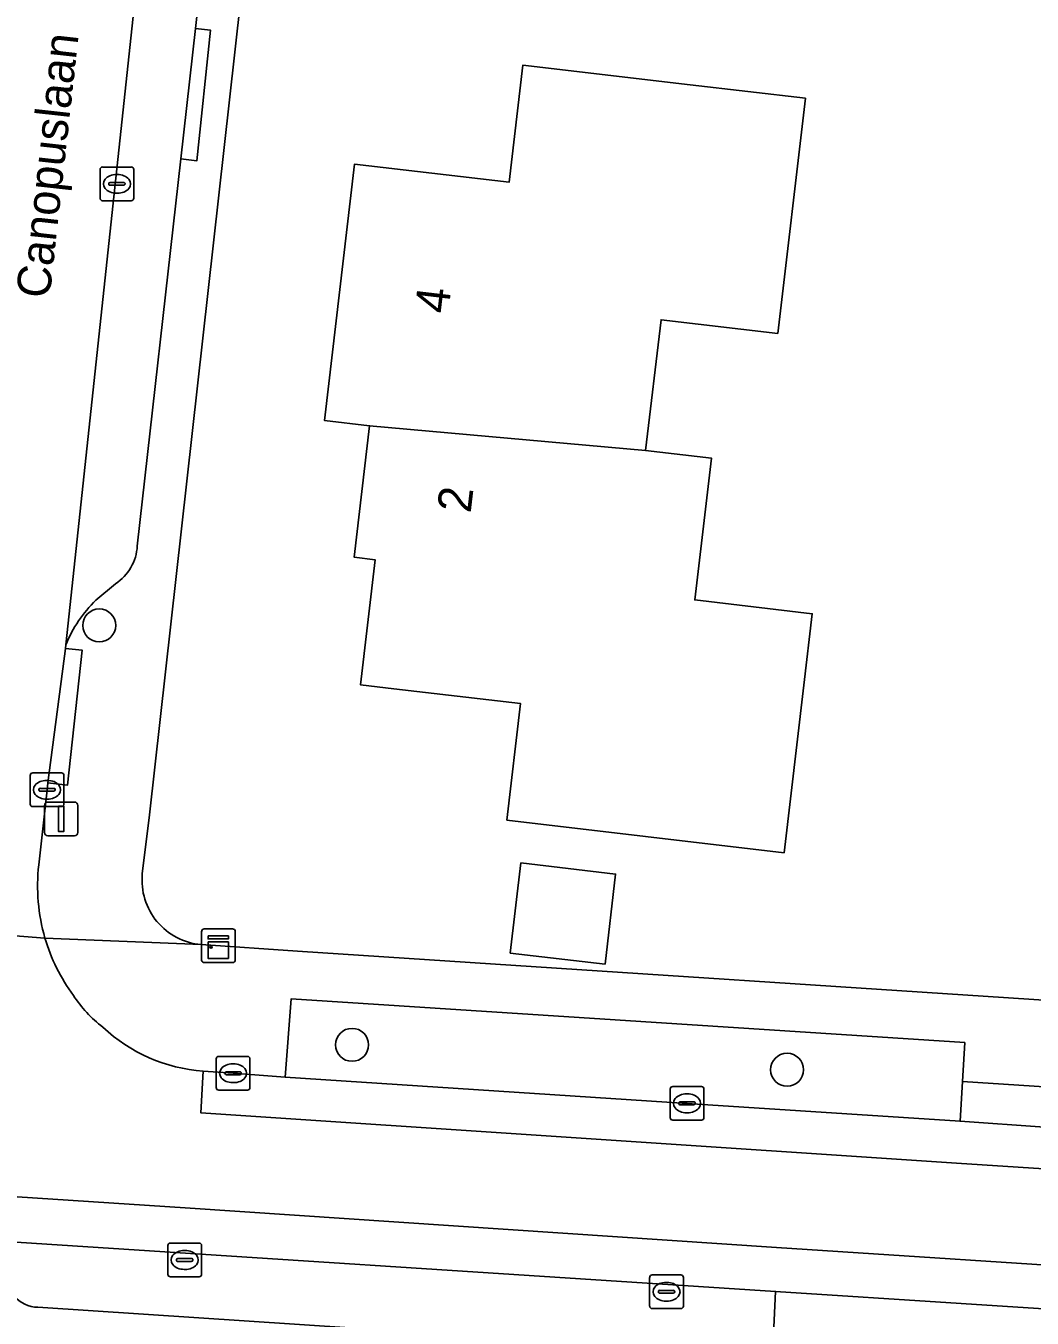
# Model space of a CAD drawing. Extents: x 162396 to 163643, y 386452 to 387406.
# Drawn here: x 162788.12 to 162817.97, y 386589.03 to 386627.35 of the extents above; entities that cross this region are included whole.
import ezdxf

# ---------------------------------------------------------------- set-up
doc = ezdxf.new("R2010")
doc.units = 0
for name, color, linetype in [('IMGEO_Boom', 7, 'Continuous'), ('IMGEO_Erf', 7, 'Continuous'), ('IMGEO_Groenvoorziening', 7, 'Continuous'), ('IMGEO_Kast', 7, 'Continuous'), ('IMGEO_Kolk', 7, 'Continuous'), ('IMGEO_Lichtmast', 7, 'Continuous'), ('IMGEO_Openbare_ruimte_label', 7, 'Continuous'), ('IMGEO_Pand', 7, 'Continuous'), ('IMGEO_Pand_nummerreeks', 7, 'Continuous'), ('IMGEO_Parkeervlak_open', 7, 'Continuous'), ('IMGEO_Rijbaan_lokaal_gesloten', 7, 'Continuous'), ('IMGEO_Rijbaan_lokaal_open', 7, 'Continuous'), ('IMGEO_Voetpad_open', 7, 'Continuous')]:
    doc.layers.add(name, color=color, linetype=linetype)

msp = doc.modelspace()

# ---------------------------------------------------------------- linework, layer by layer
at = {"layer": 'IMGEO_Boom'}
for centre in [(162790.3, 386609.571), (162797.798, 386597.132), (162810.702, 386596.395)]:
    msp.add_circle(centre, 0.489, dxfattribs=at)
at = {"layer": 'IMGEO_Erf'}
for points in [[(162796.866, 386649.291), (162791.792, 386603.958), (162791.577, 386602.199)], [(162793.321, 386600.105), (162796.177, 386599.905), (162874.812, 386594.75), (162878.183, 386594.518)]]:
    msp.add_lwpolyline(points, dxfattribs=at)
for points in [[(162810.616, 386602.831), (162802.391, 386603.797), (162802.797, 386607.252), (162799.041, 386607.693), (162798.047, 386607.81), (162798.483, 386611.518), (162797.861, 386611.591), (162798.319, 386615.492), (162796.977, 386615.65), (162797.871, 386623.255), (162802.458, 386622.716), (162802.866, 386626.188), (162807.832, 386625.604), (162811.245, 386625.203), (162810.426, 386618.229), (162806.963, 386618.636), (162806.507, 386614.763), (162808.458, 386614.534), (162807.964, 386610.325), (162811.449, 386609.916), (162811.2, 386607.797)], [(162805.303, 386599.525), (162802.493, 386599.855), (162802.807, 386602.526), (162805.617, 386602.196)]]:
    msp.add_lwpolyline(points, close=True, dxfattribs=at)
msp.add_arc((162793.486, 386602.016), 1.918, 174.527, 265.0518, dxfattribs=at)
at = {"layer": 'IMGEO_Groenvoorziening'}
msp.add_lwpolyline([(162815.975, 386597.198), (162795.992, 386598.493), (162795.81, 386596.175), (162807.735, 386595.397), (162815.835, 386594.865), (162815.902, 386596.049)], close=True, dxfattribs=at)
at = {"layer": 'IMGEO_Kast'}
for p, q in [((162793.335, 386599.645), (162793.335, 386600.486)), ((162793.335, 386600.486), (162793.335, 386599.645)), ((162793.41, 386600.57), (162794.251, 386600.57)), ((162794.251, 386600.57), (162793.41, 386600.57)), ((162794.335, 386600.495), (162794.335, 386599.654)), ((162794.335, 386599.654), (162794.335, 386600.495)), ((162794.26, 386599.57), (162793.419, 386599.57)), ((162793.419, 386599.57), (162794.26, 386599.57))]:
    msp.add_line(p, q, dxfattribs=at)
for points in [[(162793.53, 386600.36), (162794.13, 386600.36), (162794.13, 386600.275), (162793.53, 386600.275), (162793.53, 386600.36)], [(162793.53, 386600.185), (162794.13, 386600.185), (162794.13, 386599.696), (162793.53, 386599.696), (162793.53, 386600.185)]]:
    msp.add_lwpolyline(points, dxfattribs=at)
msp.add_circle((162793.614, 386600.034), 0.0377, dxfattribs=at)
for centre, start, end in [((162793.413, 386600.492), 92.4484, 184.2845), ((162793.413, 386600.492), 92.4484, 184.2845), ((162794.257, 386600.492), 2.4484, 94.2845), ((162794.257, 386600.492), 2.4484, 94.2845), ((162793.413, 386599.648), 182.4484, 274.2845), ((162793.413, 386599.648), 182.4484, 274.2845), ((162794.257, 386599.648), 272.4484, 4.2845), ((162794.257, 386599.648), 272.4484, 4.2845)]:
    msp.add_arc(centre, 0.0779, start, end, dxfattribs=at)
at = {"layer": 'IMGEO_Kolk'}
for p, q in [((162790.323, 386622.24), (162790.323, 386623.092)), ((162790.398, 386623.166), (162791.25, 386623.166)), ((162790.811, 386622.946), (162790.836, 386622.946)), ((162791.324, 386623.092), (162791.324, 386622.24)), ((162790.582, 386622.66), (162790.582, 386622.672)), ((162791.02, 386622.623), (162790.622, 386622.623)), ((162790.625, 386622.709), (162791.023, 386622.709)), ((162791.066, 386622.672), (162791.066, 386622.66)), ((162791.25, 386622.166), (162790.398, 386622.166)), ((162790.834, 386622.386), (162790.809, 386622.386)), ((162788.325, 386605.196), (162789.177, 386605.196)), ((162788.25, 386604.27), (162788.25, 386605.122)), ((162788.738, 386604.976), (162788.763, 386604.976)), ((162789.251, 386605.122), (162789.251, 386604.27)), ((162788.509, 386604.69), (162788.509, 386604.702)), ((162788.947, 386604.653), (162788.549, 386604.653)), ((162788.552, 386604.739), (162788.95, 386604.739)), ((162788.761, 386604.416), (162788.736, 386604.416)), ((162788.993, 386604.702), (162788.993, 386604.69)), ((162789.177, 386604.196), (162788.325, 386604.196)), ((162793.844, 386596.79), (162794.696, 386596.79)), ((162793.769, 386595.864), (162793.769, 386596.716)), ((162794.257, 386596.57), (162794.282, 386596.57)), ((162794.77, 386596.716), (162794.77, 386595.864)), ((162794.028, 386596.284), (162794.028, 386596.296)), ((162794.466, 386596.247), (162794.068, 386596.247)), ((162794.071, 386596.333), (162794.469, 386596.333)), ((162794.28, 386596.01), (162794.255, 386596.01)), ((162794.512, 386596.296), (162794.512, 386596.284)), ((162794.696, 386595.79), (162793.844, 386595.79)), ((162807.234, 386594.971), (162807.234, 386595.823)), ((162807.309, 386595.897), (162808.161, 386595.897)), ((162807.722, 386595.677), (162807.747, 386595.677)), ((162808.235, 386595.823), (162808.235, 386594.971)), ((162807.493, 386595.391), (162807.493, 386595.403)), ((162807.931, 386595.354), (162807.533, 386595.354)), ((162807.536, 386595.44), (162807.934, 386595.44)), ((162807.977, 386595.403), (162807.977, 386595.391)), ((162808.161, 386594.897), (162807.309, 386594.897)), ((162807.745, 386595.117), (162807.72, 386595.117)), ((162792.333, 386590.325), (162792.333, 386591.177)), ((162792.408, 386591.251), (162793.26, 386591.251)), ((162792.821, 386591.031), (162792.846, 386591.031)), ((162793.334, 386591.177), (162793.334, 386590.325)), ((162792.592, 386590.745), (162792.592, 386590.757)), ((162793.03, 386590.708), (162792.632, 386590.708)), ((162792.635, 386590.794), (162793.033, 386590.794)), ((162793.076, 386590.757), (162793.076, 386590.745)), ((162793.26, 386590.251), (162792.408, 386590.251)), ((162792.844, 386590.471), (162792.819, 386590.471)), ((162806.626, 386589.382), (162806.626, 386590.234)), ((162806.701, 386590.308), (162807.553, 386590.308)), ((162807.627, 386590.234), (162807.627, 386589.382)), ((162806.928, 386589.851), (162807.326, 386589.851)), ((162807.114, 386590.088), (162807.139, 386590.088)), ((162806.885, 386589.802), (162806.885, 386589.814)), ((162807.323, 386589.765), (162806.925, 386589.765)), ((162807.137, 386589.528), (162807.112, 386589.528)), ((162807.369, 386589.814), (162807.369, 386589.802)), ((162807.553, 386589.308), (162806.701, 386589.308))]:
    msp.add_line(p, q, dxfattribs=at)
for points in [[(162790.323, 386622.24), (162790.323, 386623.092)], [(162790.398, 386623.166), (162791.25, 386623.166)], [(162791.324, 386623.092), (162791.324, 386622.24)], [(162791.25, 386622.166), (162790.398, 386622.166)], [(162788.325, 386605.196), (162789.177, 386605.196)], [(162788.25, 386604.27), (162788.25, 386605.122)], [(162789.251, 386605.122), (162789.251, 386604.27)], [(162789.177, 386604.196), (162788.325, 386604.196)], [(162793.844, 386596.79), (162794.696, 386596.79)], [(162793.769, 386595.864), (162793.769, 386596.716)], [(162794.77, 386596.716), (162794.77, 386595.864)], [(162794.696, 386595.79), (162793.844, 386595.79)], [(162807.234, 386594.971), (162807.234, 386595.823)], [(162807.309, 386595.897), (162808.161, 386595.897)], [(162808.235, 386595.823), (162808.235, 386594.971)], [(162808.161, 386594.897), (162807.309, 386594.897)], [(162792.333, 386590.325), (162792.333, 386591.177)], [(162792.408, 386591.251), (162793.26, 386591.251)], [(162793.334, 386591.177), (162793.334, 386590.325)], [(162793.26, 386590.251), (162792.408, 386590.251)], [(162806.626, 386589.382), (162806.626, 386590.234)], [(162806.701, 386590.308), (162807.553, 386590.308)], [(162807.627, 386590.234), (162807.627, 386589.382)], [(162807.553, 386589.308), (162806.701, 386589.308)]]:
    msp.add_lwpolyline(points, dxfattribs=at)
for centre, radius, start, end in [((162790.4, 386623.09), 0.0765, 91.552, 178.448), ((162790.4, 386623.09), 0.0765, 91.552, 178.448), ((162791.248, 386623.09), 0.0765, 1.552, 88.448), ((162791.248, 386623.09), 0.0765, 1.552, 88.448), ((162790.622, 386622.669), 0.0403, 85.8775, 175.7526), ((162790.619, 386622.659), 0.0366, 178.938, 274.7102), ((162791.023, 386622.666), 0.043, 264.8664, 352.4533), ((162791.027, 386622.671), 0.0386, 1.7309, 96.639), ((162790.4, 386622.242), 0.0765, 181.552, 268.448), ((162790.4, 386622.242), 0.0765, 181.552, 268.448), ((162791.248, 386622.242), 0.0765, 271.552, 358.448), ((162791.248, 386622.242), 0.0765, 271.552, 358.448), ((162788.327, 386605.12), 0.0765, 91.552, 178.448), ((162788.327, 386605.12), 0.0765, 91.552, 178.448), ((162789.175, 386605.12), 0.0765, 1.552, 88.448), ((162789.175, 386605.12), 0.0765, 1.552, 88.448), ((162788.549, 386604.699), 0.0403, 85.8775, 175.7526), ((162788.546, 386604.689), 0.0366, 178.938, 274.7102), ((162788.95, 386604.696), 0.043, 264.8664, 352.4533), ((162788.954, 386604.701), 0.0386, 1.7309, 96.639), ((162788.327, 386604.272), 0.0765, 181.552, 268.448), ((162788.327, 386604.272), 0.0765, 181.552, 268.448), ((162789.175, 386604.272), 0.0765, 271.552, 358.448), ((162789.175, 386604.272), 0.0765, 271.552, 358.448), ((162793.846, 386596.714), 0.0765, 91.552, 178.448), ((162793.846, 386596.714), 0.0765, 91.552, 178.448), ((162794.694, 386596.714), 0.0765, 1.552, 88.448), ((162794.694, 386596.714), 0.0765, 1.552, 88.448), ((162794.068, 386596.293), 0.0403, 85.8775, 175.7526), ((162794.065, 386596.283), 0.0366, 178.938, 274.7102), ((162794.469, 386596.29), 0.043, 264.8664, 352.4533), ((162794.473, 386596.295), 0.0386, 1.7309, 96.639), ((162793.846, 386595.866), 0.0765, 181.552, 268.448), ((162793.846, 386595.866), 0.0765, 181.552, 268.448), ((162794.694, 386595.866), 0.0765, 271.552, 358.448), ((162794.694, 386595.866), 0.0765, 271.552, 358.448), ((162807.311, 386595.821), 0.0765, 91.552, 178.448), ((162807.311, 386595.821), 0.0765, 91.552, 178.448), ((162808.159, 386595.821), 0.0765, 1.552, 88.448), ((162808.159, 386595.821), 0.0765, 1.552, 88.448), ((162807.533, 386595.4), 0.0403, 85.8775, 175.7526), ((162807.53, 386595.39), 0.0366, 178.938, 274.7102), ((162807.934, 386595.397), 0.043, 264.8664, 352.4533), ((162807.938, 386595.402), 0.0386, 1.7309, 96.639), ((162807.311, 386594.973), 0.0765, 181.552, 268.448), ((162807.311, 386594.973), 0.0765, 181.552, 268.448), ((162808.159, 386594.973), 0.0765, 271.552, 358.448), ((162808.159, 386594.973), 0.0765, 271.552, 358.448), ((162792.41, 386591.175), 0.0765, 91.552, 178.448), ((162792.41, 386591.175), 0.0765, 91.552, 178.448), ((162793.258, 386591.175), 0.0765, 1.552, 88.448), ((162793.258, 386591.175), 0.0765, 1.552, 88.448), ((162792.632, 386590.754), 0.0403, 85.8775, 175.7526), ((162792.629, 386590.744), 0.0366, 178.938, 274.7102), ((162793.033, 386590.751), 0.043, 264.8664, 352.4533), ((162793.037, 386590.756), 0.0386, 1.7309, 96.639), ((162792.41, 386590.327), 0.0765, 181.552, 268.448), ((162792.41, 386590.327), 0.0765, 181.552, 268.448), ((162793.258, 386590.327), 0.0765, 271.552, 358.448), ((162793.258, 386590.327), 0.0765, 271.552, 358.448), ((162806.703, 386590.232), 0.0765, 91.552, 178.448), ((162806.703, 386590.232), 0.0765, 91.552, 178.448), ((162807.551, 386590.232), 0.0765, 1.552, 88.448), ((162807.551, 386590.232), 0.0765, 1.552, 88.448), ((162806.925, 386589.811), 0.0403, 85.8775, 175.7526), ((162807.33, 386589.813), 0.0386, 1.7309, 96.639), ((162806.922, 386589.801), 0.0366, 178.938, 274.7102), ((162807.326, 386589.808), 0.043, 264.8664, 352.4533), ((162806.703, 386589.384), 0.0765, 181.552, 268.448), ((162806.703, 386589.384), 0.0765, 181.552, 268.448), ((162807.551, 386589.384), 0.0765, 271.552, 358.448), ((162807.551, 386589.384), 0.0765, 271.552, 358.448)]:
    msp.add_arc(centre, radius, start, end, dxfattribs=at)
for centre, major_axis, ratio, start_param, end_param in [((162790.81, 386622.666), (-0.387, 0.002), 0.722429, 4.712389, 7.853982), ((162790.835, 386622.666), (-0.39, 0.002), 0.717154, 1.570796, 4.712389), ((162788.737, 386604.696), (-0.387, 0.002), 0.722429, 4.712389, 7.853982), ((162788.762, 386604.696), (-0.39, 0.002), 0.717154, 1.570796, 4.712389), ((162794.256, 386596.29), (-0.387, 0.002), 0.722429, 4.712389, 7.853982), ((162794.281, 386596.29), (-0.39, 0.002), 0.717154, 1.570796, 4.712389), ((162807.721, 386595.397), (-0.387, 0.002), 0.722429, 4.712389, 7.853982), ((162807.746, 386595.397), (-0.39, 0.002), 0.717154, 1.570796, 4.712389), ((162792.82, 386590.751), (-0.387, 0.002), 0.722429, 4.712389, 7.853982), ((162792.845, 386590.751), (-0.39, 0.002), 0.717154, 1.570796, 4.712389), ((162807.113, 386589.808), (-0.387, 0.002), 0.722429, 4.712389, 7.853982), ((162807.138, 386589.808), (-0.39, 0.002), 0.717154, 1.570796, 4.712389)]:
    msp.add_ellipse(centre, major_axis=major_axis, ratio=ratio, start_param=start_param, end_param=end_param, dxfattribs=at)
at = {"layer": 'IMGEO_Lichtmast'}
for p, q in [((162788.674, 386603.433), (162788.674, 386604.233)), ((162788.674, 386604.233), (162788.674, 386603.433)), ((162788.774, 386604.333), (162789.564, 386604.333)), ((162789.564, 386604.333), (162788.774, 386604.333)), ((162789.664, 386604.233), (162789.664, 386603.433)), ((162789.664, 386603.433), (162789.664, 386604.233)), ((162789.564, 386603.333), (162788.774, 386603.333)), ((162788.774, 386603.333), (162789.564, 386603.333))]:
    msp.add_line(p, q, dxfattribs=at)
msp.add_lwpolyline([(162789.094, 386604.208), (162789.244, 386604.208), (162789.244, 386603.458), (162789.094, 386603.458), (162789.094, 386604.208)], dxfattribs=at)
for centre, start, end in [((162788.774, 386604.233), 90, 180), ((162788.774, 386604.233), 90, 180), ((162789.564, 386604.233), 0, 90), ((162789.564, 386604.233), 360, 90), ((162788.774, 386603.433), 180, 270), ((162788.774, 386603.433), 180, 270), ((162789.564, 386603.433), 270, 0), ((162789.564, 386603.433), 270, 0)]:
    msp.add_arc(centre, 0.1, start, end, dxfattribs=at)
at = {"layer": 'IMGEO_Pand'}
for points in [[(162806.507, 386614.763), (162806.963, 386618.636), (162810.426, 386618.229), (162811.245, 386625.203), (162807.832, 386625.604), (162802.866, 386626.188), (162802.458, 386622.716), (162797.871, 386623.255), (162796.977, 386615.65), (162798.319, 386615.492)], [(162798.319, 386615.492), (162797.861, 386611.591), (162798.483, 386611.518), (162798.047, 386607.81), (162799.041, 386607.693), (162802.797, 386607.252), (162802.391, 386603.797), (162810.616, 386602.831), (162811.2, 386607.797), (162811.449, 386609.916), (162807.964, 386610.325), (162808.458, 386614.534), (162806.507, 386614.763)], [(162802.493, 386599.855), (162805.303, 386599.525), (162805.617, 386602.196), (162802.807, 386602.526)]]:
    msp.add_lwpolyline(points, close=True, dxfattribs=at)
at = {"layer": 'IMGEO_Parkeervlak_open'}
for points in [[(162793.353, 386646.739), (162789.312, 386608.996)], [(162791.429, 386611.926), (162792.724, 386623.407), (162793.152, 386627.272), (162794.92, 386643.249)], [(162790.2, 386610.319), (162790.786, 386610.806)], [(162788.479, 386589.349), (162810.269, 386587.907), (162810.36, 386589.818), (162785.991, 386591.401)]]:
    msp.add_lwpolyline(points, dxfattribs=at)
for centre, radius, start, end in [((162789.99, 386612.008), 1.441, 303.5218, 356.7573), ((162792.836, 386607.59), 3.794, 134.0084, 158.2524), ((162788.492, 386590.284), 0.935, 220.1594, 269.2184)]:
    msp.add_arc(centre, radius, start, end, dxfattribs=at)
at = {"layer": 'IMGEO_Rijbaan_lokaal_gesloten'}
for points in [[(162792.843, 386592.298), (162779.404, 386593.181), (162758.459, 386594.528), (162742.035, 386595.583), (162729.422, 386596.356), (162729.341, 386595.142)], [(162847.122, 386587.208), (162847.418, 386587.095), (162847.539, 386588.706), (162827.674, 386589.983), (162821.296, 386590.405), (162810.392, 386591.122), (162792.843, 386592.298)], [(162785.991, 386591.401), (162810.36, 386589.818), (162821.37, 386589.103), (162845.666, 386587.525)]]:
    msp.add_lwpolyline(points, dxfattribs=at)
msp.add_lwpolyline([(162844.539, 386592.844), (162842.82, 386593.006), (162836.05, 386593.531), (162828.135, 386594.063), (162820.841, 386594.51), (162815.835, 386594.865), (162807.735, 386595.397), (162795.81, 386596.175), (162794.27, 386596.29), (162793.383, 386596.353), (162793.309, 386595.117), (162815.732, 386593.621), (162828.377, 386592.8), (162836.628, 386592.258), (162846.8, 386591.41), (162851.441, 386590.986), (162864.715, 386589.801), (162884.813, 386588.054), (162884.913, 386589.288), (162881.325, 386589.597), (162867.921, 386590.772), (162864.854, 386591.05), (162857.433, 386591.68)], close=True, dxfattribs=at)
at = {"layer": 'IMGEO_Rijbaan_lokaal_open'}
for points in [[(162788.751, 386604.696), (162788.778, 386604.898), (162789.3, 386608.888), (162789.312, 386608.996), (162793.353, 386646.739), (162793.842, 386649.775)], [(162788.506, 386602.466), (162788.751, 386604.696)], [(162782.811, 386600.756), (162788.689, 386600.3)], [(162788.689, 386600.3), (162782.811, 386600.756)], [(162777.205, 386597.414), (162777.106, 386596.182), (162742.964, 386598.357), (162729.614, 386599.202), (162729.422, 386596.356), (162742.035, 386595.583), (162758.459, 386594.528), (162779.404, 386593.181), (162792.843, 386592.298), (162810.392, 386591.122), (162821.296, 386590.405), (162827.674, 386589.983), (162847.539, 386588.706), (162847.418, 386587.095), (162847.502, 386587.063), (162848.895, 386586.285)], [(162815.732, 386593.621), (162793.309, 386595.117), (162793.383, 386596.353)], [(162862.955, 386585.795), (162863.046, 386587.104), (162884.585, 386585.214), (162884.813, 386588.054), (162864.715, 386589.801), (162851.441, 386590.986), (162846.8, 386591.41), (162836.628, 386592.258), (162828.377, 386592.8), (162815.732, 386593.621)]]:
    msp.add_lwpolyline(points, dxfattribs=at)
msp.add_lwpolyline([(162821.37, 386589.103), (162810.36, 386589.818), (162810.269, 386587.907), (162821.202, 386587.174)], close=True, dxfattribs=at)
for centre, radius, start, end in [((162793.949, 386601.835), 5.479, 173.3886, 196.27), ((162793.931, 386601.837), 5.463, 196.3376, 216.3608), ((162792.604, 386600.58), 3.656, 212.8237, 233.0788), ((162793.716, 386601.158), 4.817, 226.6256, 266.0369)]:
    msp.add_arc(centre, radius, start, end, dxfattribs=at)
at = {"layer": 'IMGEO_Voetpad_open'}
for points in [[(162791.577, 386602.199), (162791.792, 386603.958), (162796.866, 386649.291)], [(162794.92, 386643.249), (162793.152, 386627.272), (162793.603, 386627.221), (162793.197, 386623.354), (162792.724, 386623.407), (162791.429, 386611.926)], [(162790.786, 386610.806), (162790.2, 386610.319)], [(162789.312, 386608.996), (162789.3, 386608.888), (162789.796, 386608.832), (162789.354, 386604.833), (162788.778, 386604.898), (162788.751, 386604.696), (162788.506, 386602.466)], [(162788.689, 386600.3), (162793.321, 386600.105)], [(162796.177, 386599.905), (162793.321, 386600.105), (162788.689, 386600.3)], [(162878.183, 386594.518), (162874.812, 386594.75), (162796.177, 386599.905)], [(162793.383, 386596.353), (162794.27, 386596.29), (162795.81, 386596.175), (162795.992, 386598.493), (162815.975, 386597.198), (162815.902, 386596.049), (162820.916, 386595.714), (162821.025, 386596.875), (162836.278, 386596.048), (162836.234, 386594.736), (162842.934, 386594.204), (162843.035, 386595.429), (162857.658, 386594.461), (162857.528, 386592.874), (162864.943, 386592.226), (162865.081, 386593.973), (162886.151, 386592.618), (162886.437, 386597.323), (162885.026, 386598.614), (162885.003, 386598.636), (162884.974, 386598.604), (162883.647, 386597.143)], [(162844.212, 386585.667), (162827.484, 386586.769), (162821.202, 386587.174), (162821.135, 386585.978), (162810.188, 386586.71), (162810.269, 386587.907), (162788.479, 386589.349)]]:
    msp.add_lwpolyline(points, dxfattribs=at)
for points in [[(162793.603, 386627.221), (162793.152, 386627.272), (162792.724, 386623.407), (162793.197, 386623.354)], [(162789.796, 386608.832), (162789.3, 386608.888), (162788.778, 386604.898), (162789.354, 386604.833)], [(162820.916, 386595.714), (162815.902, 386596.049), (162815.835, 386594.865), (162820.841, 386594.51)]]:
    msp.add_lwpolyline(points, close=True, dxfattribs=at)
for centre, radius, start, end in [((162789.99, 386612.008), 1.441, 303.5218, 356.7573), ((162792.836, 386607.59), 3.794, 134.0084, 158.2524), ((162793.949, 386601.835), 5.479, 173.3886, 196.27), ((162793.486, 386602.016), 1.918, 174.527, 265.0518), ((162793.931, 386601.837), 5.463, 196.3376, 216.3608), ((162792.604, 386600.58), 3.656, 212.8237, 233.0788), ((162793.716, 386601.158), 4.817, 226.6256, 266.0369), ((162788.492, 386590.284), 0.935, 220.1594, 269.2184)]:
    msp.add_arc(centre, radius, start, end, dxfattribs=at)

# ---------------------------------------------------------------- texts
at = {"layer": 'IMGEO_Openbare_ruimte_label'}
msp.add_text('Canopuslaan', height=1, rotation=83.6851, dxfattribs=at).set_placement((162788.822, 386619.244))
at = {"layer": 'IMGEO_Pand_nummerreeks'}
for s, rotation, p in [('4', 83.2954, (162800.65, 386618.797)), ('2', 83.3038, (162801.315, 386612.884))]:
    msp.add_text(s, height=1, rotation=rotation, dxfattribs=at).set_placement(p)

doc.saveas('drawing.dxf')
